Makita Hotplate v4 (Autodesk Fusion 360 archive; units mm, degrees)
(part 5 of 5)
sketch "Cam Thru" plane through (0, 21.7, 0) normal (0, 1, 0) x axis (-1, 0, 0)
  line L1 (0.8366, 36.2185) -> (-6.8436, 39.7998)
  line L2 (-1.1241, 49.7064) -> (5.8176, 44.8458)
  line L3 (-25.7201, 47.5685) -> (-23.2876, 49.6096)
  line L4 (-25.1687, 44.4413) -> (-25.7201, 47.5685)
  line L5 (-22.1848, 43.3553) -> (-25.1687, 44.4413)
  line L6 (-19.7522, 45.3964) -> (-22.1848, 43.3553)
  line L7 (-20.3036, 48.5236) -> (-19.7522, 45.3964)
  line L8 (-23.2876, 49.6096) -> (-20.3036, 48.5236)
  line L9 (-20, 54) -> (-22.7362, 46.4825)
  line L10 (-20, 70.55) -> (-20, 54)
  line L11 (6.1251, 40.75) -> (4.5374, 43.5)
  line L12 (4.5374, 38) -> (6.1251, 40.75)
  line L13 (1.362, 38) -> (4.5374, 38)
  line L14 (-0.2258, 40.75) -> (1.362, 38)
  line L15 (1.362, 43.5) -> (-0.2258, 40.75)
  line L16 (4.5374, 43.5) -> (1.362, 43.5)
  curve K1 (-11.8397, 39.6017) -> (-6.8436, 39.7998)
  curve K2 (-1.1241, 49.7064) -> (-3.4505, 54.1322)
  line L17 (-14.6263, 51.6906) -> (-10.6263, 49.3812)
  line L18 (-14.6263, 56.3094) -> (-14.6263, 51.6906)
  line L19 (-10.6263, 58.6188) -> (-14.6263, 56.3094)
  line L20 (-6.6263, 56.3094) -> (-10.6263, 58.6188)
  line L21 (-6.6263, 51.6906) -> (-6.6263, 56.3094)
  line L22 (-10.6263, 49.3812) -> (-6.6263, 51.6906)
  arc A1 centre (-20, 54) radius 16.55 clockwise from (-11.8397, 39.6017) to (-3.4505, 54.1322)
  arc A2 centre (2.9497, 40.75) radius 5 clockwise from (5.8176, 44.8458) to (0.8366, 36.2185)
  circle C1 centre (-22.7362, 46.4825) radius 3
  circle C2 centre (-22.7362, 46.4825) radius 1.625
  point P10 (-22.7362, 46.4825)
  point P18 (-22.7362, 46.4825)
  point P19 (-22.7362, 46.4825)
  point P4 (-20, 54)
  point P20 (-20, 54)
  point P22 (-20, 70.55)
  point P21 (-20, 54)
  point P15 (-22.1848, 43.3553)
  concentric C1 C2
  coincident P10 P18
  coincident P18 P19
  coincident P4 P20
  perpendicular L8 L9
  coincident A1 P22
  vertical L10
  coincident P20 P21
  dimension "d2589" diameter C1 = 6
  dimension "d2590" diameter C2 = 3.25
  dimension "d2591" distance P15 L8 = 5.5
  dimension "d2593" distance P19 P20 = 8
  dimension "d2795" = 200
extrude "Extrude241" cut sketch "Cam Thru" profile of C2 to an object
extrude "Extrude242" cut sketch "Cam Thru" profile of C2 L3 L4 L5 L6 L7 L8 to an object offset -20
chamfer "Chamfer34" distance 1.45
chamfer "Chamfer35" distance 1.5
circular_pattern "C-Pattern9" TotalAngle 360
sketch "Circuit City" plane through (0, 0, 0) normal (0, 1, 0) x axis (1, 0, 0)
  line L1 (-35, 0) -> (-35, -120)
  line L2 (-35, -120) -> (35, -120)
  line L3 (35, -120) -> (35, 0)
  line L4 (35, 0) -> (-35, 0)
  line L5 (-34.5, -45.6) -> (-34.5, -60)
  line L6 (-33.55, -45.6) -> (-34.5, -45.6)
  line L7 (-33.55, -43.6) -> (-33.55, -45.6)
  line L8 (-30.45, -43.6) -> (-33.55, -43.6)
  line L9 (-30.45, -44.1) -> (-30.45, -43.6)
  line L10 (-28, -44.1) -> (-30.45, -44.1)
  line L11 (-28, -23.5) -> (-28, -44.1)
  line L12 (-37.5, -23.5) -> (-28, -23.5)
  line L13 (-37.5, -60) -> (-37.5, -23.5)
  line L14 (-34.5, -60) -> (-37.5, -60)
  line L15 (-34.5, -74.4) -> (-34.5, -60)
  line L16 (-33.55, -74.4) -> (-34.5, -74.4)
  line L17 (-33.55, -76.4) -> (-33.55, -74.4)
  line L18 (-30.45, -76.4) -> (-33.55, -76.4)
  line L19 (-30.45, -75.9) -> (-30.45, -76.4)
  line L20 (-28, -75.9) -> (-30.45, -75.9)
  line L21 (-28, -96.5) -> (-28, -75.9)
  line L22 (-37.5, -96.5) -> (-28, -96.5)
  line L23 (-37.5, -60) -> (-37.5, -96.5)
  line L24 (-32, -76.4) -> (-32, -43.6)
  line L25 (-35.25, -23.5) -> (-35.25, -96.5)
  line L26 (-32, -89.2668) -> (-29.2, -90.8834)
  line L27 (-34.8, -90.8834) -> (-32, -89.2668)
  line L28 (-34.8, -94.1166) -> (-34.8, -90.8834)
  line L29 (-32, -95.7332) -> (-34.8, -94.1166)
  line L30 (-29.2, -94.1166) -> (-32, -95.7332)
  line L31 (-29.2, -90.8834) -> (-29.2, -94.1166)
  line L32 (-34.8, -29.1166) -> (-32, -30.7332)
  line L33 (-34.8, -25.8834) -> (-34.8, -29.1166)
  line L34 (-32, -24.2668) -> (-34.8, -25.8834)
  line L35 (-29.2, -25.8834) -> (-32, -24.2668)
  line L36 (-32, -30.7332) -> (-29.2, -29.1166)
  line L37 (-29.2, -29.1166) -> (-29.2, -25.8834)
  line L38 (-38, -39.5) -> (-38, -80.5)
  line L39 (-38, -39.5) -> (-38, -22.5)
  line L40 (-38, -97.5) -> (-38, -80.5)
  line L41 (-20, -22.5) -> (-38, -22.5)
  line L42 (-20, -23.5) -> (-20, -22.5)
  line L43 (-28, -23.5) -> (-20, -23.5)
  line L44 (-37, -40.5) -> (-38, -40.5)
  line L45 (-37, -23.5) -> (-37, -40.5)
  line L46 (-27.5, -25.17) -> (-20, -25.17)
  line L47 (-27.5, -94.83) -> (-27.5, -25.17)
  line L48 (-20, -26.17) -> (-20, -25.17)
  line L49 (-26.75, -26.17) -> (-20, -26.17)
  line L50 (-26.75, -93.83) -> (-26.75, -26.17)
  line L51 (-20, -93.83) -> (-26.75, -93.83)
  line L52 (-20, -94.83) -> (-20, -93.83)
  line L53 (-27.5, -94.83) -> (-20, -94.83)
  line L54 (-37, -79.5) -> (-38, -79.5)
  line L55 (-37, -96.5) -> (-37, -79.5)
  line L56 (-28, -96.5) -> (-20, -96.5)
  line L57 (-20, -97.5) -> (-38, -97.5)
  line L58 (-20, -97.5) -> (-20, -96.5)
  line L59 (-30.45, -45.6) -> (-33.55, -45.6)
  line L60 (-30.45, -44.1) -> (-30.45, -45.6)
  line L61 (-30.45, -74.4) -> (-33.55, -74.4)
  line L62 (-30.45, -75.9) -> (-30.45, -74.4)
  line L63 (-14.5, -120) -> (-14.5, -22.5)
  line L64 (-14.5, -22.5) -> (-20, -22.5)
  line L65 (-36, -120) -> (-35, -120)
  line L66 (-36, -97.5) -> (-36, -120)
  circle C1 centre (-32, -92.5) radius 1.625
  circle C2 centre (-32, -92.5) radius 3
  circle C3 centre (-32, -27.5) radius 1.625
  circle C4 centre (-32, -27.5) radius 3
  circle C5 centre (-25, -108) radius 4.25
  point P10 (-34.5, -60)
  point P20 (-34.5, -60)
  point P21 (-34.5, -60)
  point P11 (-34.5, -45.6)
  point P22 (-34.5, -74.4)
  point P12 (-33.55, -45.6)
  point P23 (-33.55, -74.4)
  point P13 (-33.55, -43.6)
  point P24 (-33.55, -76.4)
  point P14 (-30.45, -43.6)
  point P25 (-30.45, -76.4)
  point P15 (-30.45, -44.1)
  point P26 (-30.45, -75.9)
  point P16 (-28, -44.1)
  point P27 (-28, -75.9)
  point P17 (-28, -23.5)
  point P28 (-28, -96.5)
  point P18 (-37.5, -23.5)
  point P29 (-37.5, -96.5)
  point P19 (-37.5, -60)
  point P30 (-37.5, -60)
  point P31 (-32, -43.6)
  point P32 (-32, -43.6)
  point P33 (-32, -76.4)
  point P34 (-32, -60)
  point P35 (-35.25, -96.5)
  point P36 (-35.25, -23.5)
  point P37 (-32, -92.5)
  point P45 (-32, -92.5)
  point P38 (-32, -92.5)
  point P39 (-29.2, -90.8834)
  point P52 (-29.2, -29.1166)
  point P40 (-32, -89.2668)
  point P47 (-32, -30.7332)
  point P41 (-34.8, -90.8834)
  point P48 (-34.8, -29.1166)
  point P42 (-34.8, -94.1166)
  point P49 (-34.8, -25.8834)
  point P43 (-32, -95.7332)
  point P50 (-32, -24.2668)
  point P44 (-29.2, -94.1166)
  point P51 (-29.2, -25.8834)
  point P61 (-28, -23.5)
  point P58 (-38, -22.5)
  point P62 (-38, -40.5)
  point P64 (-37, -23.5)
  point P67 (-27.5, -94.83)
  point P73 (-27.5, -94.83)
  point P60 (-20, -23.5)
  point P74 (-38, -79.5)
  point P78 (-28, -96.5)
  point P63 (-37, -40.5)
  point P76 (-37, -96.5)
  point P79 (-38, -97.5)
  point P72 (-20, -94.83)
  point P82 (-30.45, -44.1)
  point P84 (-30.45, -75.9)
  point P86 (-14.5, -120)
  point P85 (-14.5, -22.5)
  point P87 (-14.5, -22.5)
  point P2 (-35, -120)
  point P89 (-35, -120)
  point P91 (-36, -97.5)
  point P65 (-20, -25.17)
  point P68 (-20, -26.17)
  point P55 (-38, -39.5)
  point P54 (-38, -80.5)
  point P77 (-20, -96.5)
  point P88 (-25, -108)
  point P90 (-36, -120)
  vertical L5
  perpendicular L5 L6
  perpendicular L6 L7
  perpendicular L7 L8
  perpendicular L8 L9
  perpendicular L9 L10
  perpendicular L10 L11
  perpendicular L11 L12
  perpendicular L12 L13
  perpendicular L11 L14
  coincident P10 P20
  symmetric P10 L14 P21
  symmetric P11 L14 P22
  symmetric P12 L14 P23
  symmetric P13 L14 P24
  symmetric P14 L14 P25
  symmetric P15 L14 P26
  symmetric P16 L14 P27
  symmetric P17 L14 P28
  symmetric P18 L14 P29
  symmetric P19 L14 P30
  midpoint L8 P31
  coincident P31 P32
  midpoint L18 P33
  midpoint L24 P34
  coincident L22 P35
  coincident L12 P36
  perpendicular L12 L25
  concentric C1 C2
  coincident P37 P45
  vertical L31
  coincident L24 P38
  symmetric L14 C1 C3
  symmetric L14 C2 C4
  symmetric L14 P39 P52
  symmetric L14 P40 P47
  symmetric L14 P41 P48
  symmetric L14 P42 P49
  symmetric L14 P43 P50
  symmetric L14 P44 P51
  perpendicular L41 L42
  coincident L11 P61
  perpendicular L11 L43
  coincident P17 P61
  coincident L39 P58
  coincident L38 P62
  perpendicular L38 L44
  coincident L12 P64
  perpendicular L12 L45
  horizontal L41
  horizontal L46
  perpendicular L46 L47
  perpendicular L46 L48
  perpendicular L48 L49
  perpendicular L49 L50
  perpendicular L48 L51
  perpendicular L51 L52
  perpendicular L52 L53
  coincident P67 P73
  coincident P60 L48
  equal L48 L52
  coincident L38 P74
  perpendicular L23 L54
  perpendicular L22 L55
  coincident P28 P78
  coincident P63 L55
  coincident L22 P76
  coincident L40 P79
  perpendicular L40 L57
  vertical L58
  coincident P72 L58
  coincident P60 L52
  horizontal L56
  perpendicular L24 L59
  perpendicular L59 L60
  coincident P15 P82
  perpendicular L24 L61
  perpendicular L61 L62
  coincident P26 P84
  coincident L2 P86
  perpendicular L2 L63
  perpendicular L42 L64
  coincident P85 P87
  coincident P2 P89
  perpendicular L1 L65
  coincident L57 P91
  perpendicular L57 L66
  dimension "d2656" distance P13 P14 = 3.1
  dimension "d2657" distance L8 P25 = 32.8 (= "32.7 mm + 0.1 mm")
  dimension "d2659" distance L5 P31 = 2.5 (= "( 4.8 / 2 ) * 1 mm + 0.1 mm")
  dimension "d2661" distance L6 P23 = 28.8 (= "28.7 mm + 0.1 mm")
  dimension "d2662" distance P14 L10 = 0.5
  dimension "d2663" distance L1 P34 = 3
  dimension "d2664" distance L1 P30 = 2.5
  dimension "d2666" distance L4 P34 = 60
  dimension "d2667" distance P18 P29 = 73
  dimension "d2668" distance L1 L25 = 0.25
  dimension "d2669" diameter C1 = 3.25
  dimension "d2670" distance L1 P17 = 7
  dimension "d2671" diameter C2 = 6
  dimension "d2672" distance P42 P44 = 5.6
  dimension "d2673" distance P34 P37 = 32.5
  dimension "d2699" distance P62 P63 = 1
  dimension "d2700" distance L41 P64 = 1
  dimension "d2701" distance P60 P61 = 8
  dimension "d2702" distance L11 L47 = 0.5
  dimension "d2703" distance L43 L46 = 1.67
  dimension "d2704" distance P65 P68 = 1
  dimension "d2705" distance L47 L50 = 0.75
  dimension "d2706" distance P55 P62 = 1 (= "d2699")
  dimension "d2707" distance P54 L54 = 1
  dimension "d2708" distance P29 L57 = 1 (= "d2700")
  dimension "d2709" distance L53 P77 = 1.67 (= "d2703")
  dimension "d2861" distance P38 L63 = 17.5
  dimension "d2865" distance P37 P88 = 7
  dimension "d2866" distance P45 P88 = 15.5
  dimension "d2867" diameter C5 = 8.5
  dimension "d2868" distance P89 P90 = 1
extrude "Extrude264" cut sketch "Circuit City" profile of L1 L2 L5 L6 L7 L8 L9 L10 L11 L12 L13 L15 L16 L17 L18 L19 L20 L21 L22 L23 L25 C1 L26 L27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 to an object offset 2.5
extrude "Extrude248" sketch "Circuit City" profile of L1 L5 L6 L7 L8 L9 L10 L11 L12 L15 L16 L17 L18 L19 L20 L21 L22 L25 C1 L26 L27 L28 L29 L30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 blind -6.75 from offset 1.6 bodies "Circuit Cap"
extrude "Extrude249" sketch "Circuit City" profile of L12 L13 L22 L23 L25 L44 L45 L54 L55 to an object from offset 0.1
extrude "Extrude251" cut sketch "Circuit City" profile of C1 C3 to an object
extrude "Extrude256" sketch "Circuit City" profile of L1 L5 L6 L7 L8 L9 L10 L11 L12 L13 L15 L16 L17 L18 L19 L20 L21 L22 L23 L25 C1 L26 L27 L28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 blind -0.5
extrude "Extrude250" sketch "Circuit City" profile of C1 L26 L27 L28 L29 L30 L31 C3 L32 L33 L34 L35 L36 L37 to an object offset 15
fillet "Fillet121" radius 2
chamfer "Chamfer44" distance 1.6
chamfer "Chamfer48" distance 1.45
extrude "Extrude252" sketch "Circuit City" profile of L1 L12 L13 L22 L23 L38 L39 L40 L41 L42 L43 L44 L45 L46 L47 L48 L49 L50 L51 L52 L53 L54 L55 L56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 to an object
fillet "Fillet122" radius 0.5
sketch "Pushrod Space" plane through (0, 22.2, 0) normal (0, 1, 0) x axis (-1, 0, 0)
  line L1 (41.5262, 38.2356) -> (39.8025, 35.25)
  line L2 (44.9738, 38.2356) -> (41.5262, 38.2356)
  line L3 (46.6975, 35.25) -> (44.9738, 38.2356)
  line L4 (44.9738, 32.2644) -> (46.6975, 35.25)
  line L5 (41.5262, 32.2644) -> (44.9738, 32.2644)
  line L6 (39.8025, 35.25) -> (41.5262, 32.2644)
  line L7 (49.8025, 84.75) -> (51.5262, 81.7644)
  line L8 (51.5262, 87.7356) -> (49.8025, 84.75)
  line L9 (54.9738, 87.7356) -> (51.5262, 87.7356)
  line L10 (56.6975, 84.75) -> (54.9738, 87.7356)
  line L11 (54.9738, 81.7644) -> (56.6975, 84.75)
  line L12 (51.5262, 81.7644) -> (54.9738, 81.7644)
  line L13 (56.6975, 35.25) -> (54.9738, 38.2356)
  line L14 (54.9738, 32.2644) -> (56.6975, 35.25)
  line L15 (51.5262, 32.2644) -> (54.9738, 32.2644)
  line L16 (49.8025, 35.25) -> (51.5262, 32.2644)
  line L17 (51.5262, 38.2356) -> (49.8025, 35.25)
  line L18 (54.9738, 38.2356) -> (51.5262, 38.2356)
  line L19 (46.6975, 84.75) -> (44.9738, 87.7356)
  line L20 (44.9738, 81.7644) -> (46.6975, 84.75)
  line L21 (41.5262, 81.7644) -> (44.9738, 81.7644)
  line L22 (39.8025, 84.75) -> (41.5262, 81.7644)
  line L23 (41.5262, 87.7356) -> (39.8025, 84.75)
  line L24 (44.9738, 87.7356) -> (41.5262, 87.7356)
  line L25 (-35, 120) -> (58.5, 120)
  line L26 (-35, 0) -> (-35, 120)
  line L27 (58.5, 0) -> (-35, 0)
  line L28 (58.5, 39.5) -> (58.5, 0)
  line L29 (49.25, 39.5) -> (58.5, 39.5)
  line L30 (49.25, 34.25) -> (49.25, 39.5)
  line L31 (47.25, 39.5) -> (47.25, 34.25)
  line L32 (38.5, 39.5) -> (47.25, 39.5)
  line L33 (47.25, 80.5) -> (38, 80.5)
  line L34 (47.25, 85.75) -> (47.25, 80.5)
  line L35 (49.25, 80.5) -> (49.25, 85.75)
  line L36 (58.5, 80.5) -> (49.25, 80.5)
  line L37 (58.5, 120) -> (58.5, 80.5)
  line L38 (38.5, 39.5) -> (28.5, 39.5)
  line L39 (48.25, 49.75) -> (48.25, 34.25)
  line L40 (-6.5566, 23.8624) -> (-20, 54)
  line L41 (-39.9714, 27.7295) -> (-37.8295, 32.5403)
  line L42 (-37.8295, 32.5403) -> (-34.173, 40.7529)
  line L43 (28.5, 39.5) -> (-6.5566, 23.8624)
  line L44 (10.847, 42.2757) -> (6.4974, 45.2651)
  line L45 (-0.9412, 50.3775) -> (6.4974, 45.2651)
  line L46 (-45, 0) -> (-35, 0)
  line L47 (-45, 120) -> (-45, 0)
  line L48 (-35, 120) -> (-45, 120)
  line L49 (7.9, 54) -> (-20, 54)
  line L50 (3.9, 50.8246) -> (1.15, 52.4123)
  line L51 (6.65, 52.4123) -> (3.9, 50.8246)
  line L52 (6.65, 55.5877) -> (6.65, 52.4123)
  line L53 (3.9, 57.1754) -> (6.65, 55.5877)
  line L54 (1.15, 55.5877) -> (3.9, 57.1754)
  line L55 (1.15, 52.4123) -> (1.15, 55.5877)
  line L56 (17.368, 47.0482) -> (48.25, 49.75)
  line L57 (38, 79.5) -> (38, 40.5)
  line L58 (26.75, 71.2668) -> (4.8491, 46.3979)
  line L59 (27.5, 84.2668) -> (37, 84.2668)
  line L60 (20.5, 96.5) -> (36.5, 96.5)
  line L61 (37.5, 97.5) -> (20.5, 97.5)
  line L62 (38, 80.5) -> (38, 97)
  line L63 (38, 23) -> (38, 39)
  line L64 (20.5, 22.5) -> (37.5, 22.5)
  line L65 (36.5, 23.5) -> (20.5, 23.5)
  line L66 (37, 40) -> (37, 24)
  line L67 (38, 40.5) -> (37.5, 40.5)
  line L68 (37.5, 79.5) -> (38, 79.5)
  line L69 (37, 96) -> (37, 80)
  line L70 (29.2, 29.1166) -> (29.2, 25.8834)
  line L71 (32, 30.7332) -> (29.2, 29.1166)
  line L72 (34.8, 29.1166) -> (32, 30.7332)
  line L73 (34.8, 25.8834) -> (34.8, 29.1166)
  line L74 (32, 24.2668) -> (34.8, 25.8834)
  line L75 (29.2, 25.8834) -> (32, 24.2668)
  line L76 (32, 95.7332) -> (29.2, 94.1166)
  line L77 (34.8, 94.1166) -> (32, 95.7332)
  line L78 (34.8, 90.8834) -> (34.8, 94.1166)
  line L79 (32, 89.2668) -> (34.8, 90.8834)
  line L80 (29.2, 90.8834) -> (32, 89.2668)
  line L81 (29.2, 94.1166) -> (29.2, 90.8834)
  line L82 (20.5, 93.83) -> (26.25, 93.83)
  line L83 (27, 94.83) -> (20.5, 94.83)
  line L84 (27.5, 25.67) -> (27.5, 94.33)
  line L85 (20.5, 25.17) -> (27, 25.17)
  line L86 (26.25, 26.17) -> (20.5, 26.17)
  line L87 (26.75, 93.33) -> (26.75, 26.67)
  line L88 (6.1199, 25.17) -> (20.5, 25.17)
  line L89 (20.0025, 94.3798) -> (16.5264, 59.6577)
  closed curve K1 centre (52.9954, 12)
  closed curve K2 centre (52.9954, 108)
  arc A1 centre (48.25, 34.25) radius 1 clockwise from (49.25, 34.25) to (47.25, 34.25)
  arc A2 centre (48.25, 85.75) radius 1 clockwise from (47.25, 85.75) to (49.25, 85.75)
  arc A3 centre (-20, 54) radius 33 clockwise from (-6.5566, 23.8624) to (-39.9714, 27.7295)
  arc A4 centre (-17.0001, 85.9192) radius 65 clockwise from (28.5, 39.5) to (-20.2611, 21.001)
  arc A5 centre (-20, 54) radius 33 clockwise from (10.847, 42.2757) to (-6.5566, 23.8624)
  arc A6 centre (-20, 54) radius 19.4 clockwise from (-34.173, 40.7529) to (-0.9412, 50.3775)
  circle C1 centre (3.9, 54) radius 1.625
  circle C2 centre (3.9, 54) radius 3
  circle C3 centre (-20, 54) radius 27.9
  arc A7 centre (-20, 54) radius 20.9 clockwise from (-34.8313, 39.2744) to (0.4, 49.4557)
  arc A8 centre (36.5, 96) radius 0.5 clockwise from (36.5, 96.5) to (37, 96)
  arc A9 centre (20.5, 97) radius 0.5 clockwise from (20.5, 96.5) to (20.5, 97.5)
  arc A10 centre (37.5, 97) radius 0.5 clockwise from (37.5, 97.5) to (38, 97)
  arc A11 centre (38.5, 39) radius 0.5 clockwise from (38, 39) to (38.5, 39.5)
  arc A12 centre (37.5, 23) radius 0.5 clockwise from (38, 23) to (37.5, 22.5)
  arc A13 centre (20.5, 23) radius 0.5 clockwise from (20.5, 22.5) to (20.5, 23.5)
  arc A14 centre (36.5, 24) radius 0.5 clockwise from (37, 24) to (36.5, 23.5)
  arc A15 centre (37.5, 40) radius 0.5 clockwise from (37, 40) to (37.5, 40.5)
  arc A16 centre (37.5, 80) radius 0.5 clockwise from (37.5, 79.5) to (37, 80)
  arc A17 centre (26.25, 93.33) radius 0.5 clockwise from (26.25, 93.83) to (26.75, 93.33)
  arc A18 centre (20.5, 94.33) radius 0.5 clockwise from (20.5, 93.83) to (20.5, 94.83)
  arc A19 centre (27, 94.33) radius 0.5 clockwise from (27, 94.83) to (27.5, 94.33)
  arc A20 centre (27, 25.67) radius 0.5 clockwise from (27.5, 25.67) to (27, 25.17)
  arc A21 centre (20.5, 25.67) radius 0.5 clockwise from (20.5, 25.17) to (20.5, 26.17)
  arc A22 centre (26.25, 26.67) radius 0.5 clockwise from (26.75, 26.67) to (26.25, 26.17)
  point P46 (48.25, 34.25)
  point P47 (48.25, 34.25)
  point P50 (-20, 54)
  point P88 (-20, 54)
  point P53 (-20, 54)
  point P54 (-37.8295, 32.5403)
  point P56 (-37.8295, 32.5403)
  point P51 (-39.9714, 27.7295)
  point P55 (-39.9714, 27.7295)
  point P63 (28.5, 39.5)
  point P62 (-20.2611, 21.001)
  point P64 (-20, 54)
  point P49 (6.4974, 45.2651)
  point P67 (6.4974, 45.2651)
  point P52 (-6.5566, 23.8624)
  point P65 (-6.5566, 23.8624)
  point P30 (-35, 0)
  point P70 (-35, 0)
  point P29 (-35, 120)
  point P73 (-35, 120)
  point P77 (-20, 54)
  point P78 (7.9, 54)
  point P79 (3.9, 54)
  point P87 (3.9, 54)
  point P60 (28.5, 39.5)
  point P45 (38.5, 39.5)
  point P59 (38.5, 39.5)
  point P92 (0.9, 54)
  point P95 (4.8491, 46.3979)
  point P97 (2.275, 54)
  point P48 (48.25, 49.75)
  point P93 (48.25, 49.75)
  point P100 (27.5, 84.2668)
  point P157 (37, 84.2668)
  point P96 (26.75, 71.2668)
  point P151 (20.5, 25.17)
  point P158 (20.5, 25.17)
  point P159 (6.1199, 25.17)
  point P160 (16.5264, 59.6577)
  point P161 (20.0025, 94.3798)
  point P71 (-45, 0)
  point P84 (6.65, 55.5877)
  point P80 (3.9, 54)
  point P94 (17.368, 47.0482)
  point P137 (32, 89.2668)
  horizontal L38
  coincident P46 P47
  parallel L30 L39
  coincident P50 P88
  coincident P53 P88
  coincident P54 C3
  coincident P54 P56
  parallel L41 L42
  coincident P51 P55
  tangent A3 L43
  coincident L43 P63
  coincident A3 P62
  coincident P50 P64
  coincident P49 P67
  parallel L44 L45
  coincident P52 P65
  coincident P30 P70
  perpendicular L26 L46
  perpendicular L46 L47
  perpendicular L47 L48
  coincident P29 P73
  coincident P77 P88
  coincident P78 C3
  coincident L49 P79
  concentric C1 C2
  coincident P79 P87
  perpendicular L49 L55
  coincident L38 P60
  coincident P45 P59
  coincident A7 P92
  coincident L49 P92
  coincident L45 P95
  horizontal L49
  coincident C1 P97
  coincident L49 P97
  coincident P60 P63
  coincident P48 P93
  coincident P100 L84
  coincident L69 P157
  horizontal L59
  coincident P96 L87
  coincident P151 P158
  coincident A4 P159
  horizontal L88
  coincident L58 P160
  coincident A18 P161
  tangent A18 L89
  dimension "d2536" distance P47 P48 = 15.5
  dimension "d2538" radius A3 = 33
  dimension "d2539" distance P59 P60 = 10
  dimension "d2540" distance P52 P62 = 14
  dimension "d2543" radius A4 = 65
  dimension "d2588" distance P70 P71 = 10
  dimension "d2603" distance P84 L55 = 5.5
  dimension "d2604" diameter C2 = 6
  dimension "d2605" diameter C1 = 3.25
  dimension "d2636" distance L55 P92 = 0.25
  dimension "d2638" angle L39 L56 = 85
  dimension "d2741" distance P67 P95 = 2
  dimension "d2746" distance P80 P92 = 3
  dimension "d2747" distance P92 P97 = 1.375
  dimension "d2756" distance P93 P94 = 31
  dimension "d2757" distance P96 L59 = 13
  dimension "d2860" distance L59 P137 = 5
  dimension "d2870" distance P80 L89 = 12
extrude "Extrude257" cut sketch "Pushrod Space" profile of L26 C3 L42 L45 A6 C1 L50 L51 L52 L53 L54 L55 A7 L58 to an object
extrude "Extrude258" cut sketch "Pushrod Space" profile of C3 L47 to an object
extrude "Extrude259" new body sketch "Pushrod Space" profile of L26 C3 A3 L41 L46 L47 L48 to an object
combine "Combine30" bodies "Rotary Cap"
offset_faces "OffsetFaces16" distance -0.25
extrude "Extrude237" cut sketch "Pushrod Space" profile of L26 C3 A3 L43 A4 A5 L44 L45 L58 to an object
chamfer "Chamfer49" distance 2
extrude "Extrude260" cut sketch "Pushrod Space" profile of L38 A3 L43 A4 L57 L59 L66 A15 L67 L68 A16 L69 L84 A21 L86 A22 L87 L88 to an object offset 1
fillet "Fillet125" radius 7
fillet "Fillet126" radius 3
fillet "Fillet128" radius 1
extrude "Extrude243" cut sketch "Pushrod Space" profile of C1 to an object
extrude "Extrude244" sketch "Pushrod Space" profile of C1 L50 L51 L52 L53 L54 L55 blind 4.5
chamfer "Chamfer36" distance 0.5
chamfer "Chamfer37" distance 1.5
circular_pattern "C-Pattern8" countU 12 TotalAngle 360
sketch "Sketch82" plane through (0, 0, 0) normal (0, 1, 0) x axis (1, 0, 0)
  line L1 (-31.75, -107) -> (23.25, -107)
  line L2 (-31.75, -22) -> (-31.75, -107)
  line L3 (23.25, -22) -> (-31.75, -22)
  line L4 (23.25, -107) -> (23.25, -22)
  line L5 (8.25, -8) -> (8.25, -22)
  line L6 (-21.75, -8) -> (8.25, -8)
  line L7 (-21.75, -22) -> (-21.75, -8)
  line L8 (-11.75, -62) -> (-11.75, -107)
  line L9 (45, 0) -> (-58.5, 0)
  line L10 (-6.75, 0) -> (-6.75, -8)
  line L11 (-1.75, -90) -> (-1.75, 0)
  line L12 (17.25, -90) -> (-17.75, -90)
  line L13 (-1.75, -92.9585) -> (1.75, -94.9793)
  line L14 (-5.25, -94.9793) -> (-1.75, -92.9585)
  line L15 (-5.25, -99.0207) -> (-5.25, -94.9793)
  line L16 (-1.75, -101.0415) -> (-5.25, -99.0207)
  line L17 (1.75, -99.0207) -> (-1.75, -101.0415)
  line L18 (1.75, -94.9793) -> (1.75, -99.0207)
  line L19 (17.25, -8) -> (8.25, -8)
  circle C1 centre (-21.75, -8) radius 2.125
  circle C2 centre (8.25, -8) radius 2.125
  circle C3 centre (8.25, -8) radius 4.125
  circle C4 centre (23.25, -107) radius 2.125
  circle C5 centre (-31.75, -107) radius 2.125
  circle C6 centre (-31.75, -107) radius 4.5
  circle C7 centre (-11.75, -62) radius 2.125
  circle C8 centre (-16.75, -107) radius 2.125
  circle C9 centre (23.25, -107) radius 4.125
  circle C10 centre (-16.75, -107) radius 4.125
  circle C11 centre (-11.75, -62) radius 4.125
  circle C12 centre (-21.75, -8) radius 4.125
  circle C13 centre (-17.75, -90) radius 2.125
  circle C14 centre (17.25, -90) radius 2.125
  circle C15 centre (-17.75, -90) radius 4.125
  circle C16 centre (17.25, -90) radius 4.125
  circle C17 centre (-1.75, -97) radius 2.075
  circle C18 centre (17.25, -8) radius 2.125
  circle C19 centre (17.25, -8) radius 4.125
  point P6 (8.25, -22)
  point P9 (-21.75, -22)
  point P10 (-6.75, -8)
  point P8 (-21.75, -8)
  point P11 (-21.75, -8)
  point P7 (8.25, -8)
  point P12 (8.25, -8)
  point P2 (23.25, -107)
  point P14 (23.25, -107)
  point P3 (-31.75, -107)
  point P15 (-31.75, -107)
  point P17 (-11.75, -107)
  point P18 (-11.75, -62)
  point P19 (-11.75, -62)
  point P22 (-6.75, 0)
  point P23 (-6.75, -8)
  point P24 (-6.75, 0)
  point P25 (-16.75, -107)
  point P26 (23.25, -107)
  point P27 (-16.75, -107)
  point P28 (-11.75, -62)
  point P29 (-21.75, -8)
  point P30 (-1.75, 0)
  point P32 (-17.75, -90)
  point P36 (-17.75, -90)
  point P33 (17.25, -90)
  point P37 (17.25, -90)
  point P38 (-1.75, -97)
  point P45 (-1.75, -97)
  point P48 (8.25, -8)
  point P46 (17.25, -8)
  point P49 (17.25, -8)
  point P31 (-1.75, -90)
  point P1 (0, 0)
  point P44 (1.75, -99.0207)
  point P21 (45, 0)
  point P35 (17.25, -90)
  point P34 (-17.75, -90)
  point P47 (17.25, -8)
  horizontal L1
  vertical L2
  horizontal L3
  vertical L4
  coincident L3 P6
  perpendicular L3 L5
  perpendicular L5 L6
  perpendicular L3 L7
  coincident L3 P9
  midpoint L6 P10
  coincident P8 P11
  coincident P7 P12
  equal C1 C2
  concentric C2 C3
  coincident P2 P14
  coincident P3 P15
  equal C2 C5
  equal C2 C4
  concentric C5 C6
  coincident L1 P17
  perpendicular L1 L8
  coincident P18 P19
  equal C2 C7
  midpoint L9 P22
  coincident P10 P23
  coincident P22 P24
  perpendicular L9 L10
  coincident L1 P25
  equal C5 C8
  equal C9 C11
  equal C9 C12
  equal C10 C12
  equal C3 C9
  coincident P14 P26
  coincident P25 P27
  coincident P19 P28
  coincident P11 P29
  coincident L9 P30
  perpendicular L9 L11
  horizontal L12
  concentric C13 C15
  concentric C14 C16
  coincident P32 P36
  coincident P33 P37
  equal C8 C13
  equal C10 C15
  equal C9 C16
  equal C4 C14
  coincident P38 P45
  vertical L18
  concentric C18 C19
  equal C2 C18
  equal C3 C19
  coincident P12 P48
  parallel L6 L19
  coincident P46 P49
  coincident P31 L12
  dimension "d2834" distance P2 P3 = 55
  dimension "d2836" distance P1 L3 = 22
  dimension "d2838" distance P7 P8 = 30
  dimension "d2839" diameter C2 = 4.25
  dimension "d2840" diameter C3 = 8.25
  dimension "d2841" distance P17 P18 = 45
  dimension "d2845" distance L4 P22 = 30
  dimension "d2846" diameter C6 = 9
  dimension "d2879" distance L6 L9 = 8
  dimension "d2880" distance P22 P27 = 107
  dimension "d2883" distance P19 P22 = 62
  dimension "d2885" distance P30 P31 = 90
  dimension "d2887" distance P22 P30 = 5
  dimension "d2888" diameter C17 = 4.15
  dimension "d2889" distance P44 L15 = 7 (= "hw_m4hex_d")
  dimension "d2890" distance P22 P45 = 97
  dimension "d2891" distance P22 P45 = 5
  dimension "d2896" distance L1 P21 = 107
  dimension "d2900" distance P22 P35 = 24
  dimension "d2901" distance P22 P34 = 11
  dimension "d2902" distance P10 L8 = 5
  dimension "d2903" distance P22 P27 = 10
  dimension "d2904" distance P10 P47 = 24
extrude "Extrude262" cut sketch "Sketch82" profile of C1 C2 C4 C7 C8 C13 C14 C17 C18 to an object
extrude "Extrude265" sketch "Sketch82" profile of C1 C2 C3 C4 C7 C8 C9 C10 C11 C12 C13 C14 C15 C16 C18 C19 to an object from offset -0.25
chamfer "Chamfer54" distance 2 (= "( ( 8.25 - 4.25 ) / 2 ) * 1 mm")
fillet "Fillet134" radius 1
extrude "Extrude267" sketch "Sketch82" profile of C17 L13 L14 L15 L16 L17 L18 blind 8
component_from_bodies "Body->Comp5"
component_from_bodies "Body->Comp6"
joint "Assemble65" alignAngle 0 alignOffsetX 0 alignOffsetY 0 alignOffsetZ -0.5
joint "Assemble66" alignAngle 0 alignOffsetX 0 alignOffsetY 0 alignOffsetZ 0
component_insert "Component Insert64"
joint "Assemble58" alignAngle 0 alignOffsetX 0 alignOffsetY 0 alignOffsetZ 0
component_insert "Component Insert65"
joint "Assemble59" alignAngle 180 alignOffsetX 0 alignOffsetY 0 alignOffsetZ 0
component_insert "Component Insert68"
joint "Assemble67" alignAngle 180 alignOffsetX 0 alignOffsetY 0 alignOffsetZ 0
joint "Assemble68" alignAngle 180 alignOffsetX 0 alignOffsetY 0 alignOffsetZ 0
component_insert "Component Insert78"
joint "Assemble78" alignAngle 180 alignOffsetX 0 alignOffsetY 0 alignOffsetZ 0
component_insert "Component Insert79"
joint "Assemble79" alignAngle 0 alignOffsetX 0 alignOffsetY 0 alignOffsetZ -2
component_insert "Component Insert80"
joint "Assemble80" alignAngle 180 alignOffsetX 0 alignOffsetY 0 alignOffsetZ 0
component_insert "Component Insert81"
joint "Assemble81" alignAngle 180 alignOffsetX 0 alignOffsetY 0 alignOffsetZ 0
component_insert "Component Insert82"
joint "Assemble82" alignAngle 180 alignOffsetX 0 alignOffsetY 0 alignOffsetZ 0
component_insert "Component Insert83"
joint "Assemble83" alignAngle 180 alignOffsetX 0 alignOffsetY 0 alignOffsetZ 0
component_insert "Component Insert84"
joint "Assemble84" alignAngle 150 alignOffsetX 0 alignOffsetY 0 alignOffsetZ 0
component_insert "Component Insert85"
joint "Assemble85" alignAngle 210 alignOffsetX 0 alignOffsetY 0 alignOffsetZ 0
component_insert "Component Insert86"
joint "Assemble86" alignAngle 170 alignOffsetX 0 alignOffsetY 0 alignOffsetZ -1.5
component_insert "Component Insert87"
joint "Assemble87" alignAngle 200 alignOffsetX 0 alignOffsetY 0 alignOffsetZ -1.5
component_insert "Component Insert88"
joint "Assemble88" alignAngle 0 alignOffsetX 0 alignOffsetY 0 alignOffsetZ 0
component_insert "Component Insert89"
joint "Assemble89" alignAngle 0 alignOffsetX 0 alignOffsetY 0 alignOffsetZ 0
component_insert "Component Insert90"
joint "Assemble90" alignAngle 0 alignOffsetX 0 alignOffsetY 0 alignOffsetZ -1.5
component_insert "Component Insert91"
joint "Assemble91" alignAngle 0 alignOffsetX 0 alignOffsetY 0 alignOffsetZ -1.5
component_insert "Component Insert92"
joint "Assemble92" alignAngle 30 alignOffsetX 0 alignOffsetY 0 alignOffsetZ -2
component_insert "Component Insert93"
joint "Assemble93" alignAngle 0 alignOffsetX 0 alignOffsetY 0 alignOffsetZ 0
component_insert "Component Insert94"
joint "Assemble94" alignAngle 0 alignOffsetX 0 alignOffsetY 0 alignOffsetZ 0
component_insert "Component Insert76"
joint "Assemble76" alignAngle 180 alignOffsetX 0 alignOffsetY 0 alignOffsetZ 0
component_insert "Component Insert77"
joint "Assemble77" alignAngle 180 alignOffsetX 0 alignOffsetY 0 alignOffsetZ 0
component_insert "Component Insert95"
joint "Assemble95" alignAngle 180 alignOffsetX 0 alignOffsetY 0 alignOffsetZ 0
component_insert "Component Insert97"
joint "Assemble96" alignAngle 180 alignOffsetX 0 alignOffsetY 0 alignOffsetZ 0
component_insert "Component Insert98"
joint "Assemble97" alignAngle 0 alignOffsetX 0 alignOffsetY 0 alignOffsetZ 0
component_insert "Component Insert99"
joint "Assemble98" alignAngle 0 alignOffsetX 0 alignOffsetY 0 alignOffsetZ 0
component_insert "Component Insert71"
joint "Assemble70" alignAngle 0 alignOffsetX 0 alignOffsetY 0 alignOffsetZ 0
component_insert "Component Insert72"
joint "Assemble72" alignAngle 180 alignOffsetX 0 alignOffsetY 0 alignOffsetZ 0
component_insert "Component Insert70"
joint "Assemble71" alignAngle 0 alignOffsetX 0 alignOffsetY 0 alignOffsetZ 0 DistanceMinimum 0 DistanceMaximum 0
component_insert "Component Insert100"
joint "Assemble99" alignAngle 0 alignOffsetX 0 alignOffsetY 0 alignOffsetZ 0
component_insert "Component Insert102"
joint "Assemble100" alignAngle 0 alignOffsetX 0 alignOffsetY 0 alignOffsetZ 0
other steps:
base_feature "Base Feature1" bodies "HP Cam Rear"
base_feature "Base Feature1" bodies "HP Cam Front"
step "Combine15"
step "Combine16"
step "Revolve" AlongAngle 360
remove_body "Mirror7" mirrorStitchTolerance 0.1
step "Sweep2" TwistAngle 0 TaperAngle 0
step "Sweep3" TwistAngle 0 TaperAngle 0
step "Sweep4" TwistAngle 0 TaperAngle 0
remove_body "Mirror6" mirrorStitchTolerance 0.1
step "Component Insert39"
fillet "Assemble39" alignAngle 0 alignOffsetX 0 alignOffsetY 0 alignOffsetZ 0
step "WorkPlane" AlongDistance -6
step "Component Insert40"
fillet "Assemble40" alignAngle 0 alignOffsetX 0 alignOffsetY 0 alignOffsetZ 0
step "Component Insert41"
fillet "Assemble41" alignAngle 0 alignOffsetX 0 alignOffsetY 0 alignOffsetZ 0
create_component "CreateComponent5"
remove_body "RemoveBody6"
create_component "CreateComponent6"
remove_body "RemoveBody7"
joint_origin "JointOrigin1"
joint_origin "JointOrigin1"
joint_origin "JointOrigin2"
joint_origin "JointOrigin66"
joint_origin "JointOrigin6"
joint_origin "JointOrigin69"
joint_origin "JointOrigin73"
joint_origin "JointOrigin75"
joint_origin "JointOrigin76"
joint_origin "JointOrigin77"
joint_origin "JointOrigin78"
joint_origin "JointOrigin4"
joint_origin "JointOrigin7"
joint_origin "JointOrigin5"
joint_origin "JointOrigin6"
joint_origin "JointOrigin7"
joint_origin "JointOrigin79"
joint_origin "JointOrigin80"
joint_origin "JointOrigin8"
joint_origin "JointOrigin10"
joint_origin "JointOrigin11"
joint_origin "JointOrigin81"
joint_origin "JointOrigin82"
joint_origin "JointOrigin83"
joint_origin "JointOrigin84"
joint_origin "JointOrigin85"
joint_origin "JointOrigin86"
joint_origin "JointOrigin87"
named bodies: "Hotplate Body", "Rear Cap", "Rotary Cap", "HP Cam Front", "HP Cam Rear", "Circuit Cap"

design "PCB Blade Drop" references "TE-10p-2p5-blade_1123684-07"
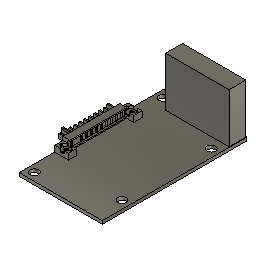
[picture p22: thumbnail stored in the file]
sketch "Sketch1" plane through (0, 0, 0) normal (0, 0, 1) x axis (1, 0, 0)
  line L1 (42, 0) -> (0, 0)
  line L2 (42, 73) -> (42, 0)
  line L3 (0, 73) -> (42, 73)
  line L4 (0, 0) -> (0, 73)
  line L5 (3.7, 20.05) -> (3.7, 52.95)
  line L6 (0, 36.5) -> (3.7, 36.5)
  line L7 (3.7, 20.05) -> (3.7, 4)
  line L8 (3.7, 69) -> (3.7, 52.95)
  line L9 (41.75, 72.75) -> (9.75, 72.75)
  line L10 (41.75, 64.25) -> (41.75, 72.75)
  line L11 (9.75, 64.25) -> (41.75, 64.25)
  line L12 (9.75, 72.75) -> (9.75, 64.25)
  line L13 (31.25, 70.5) -> (20.25, 70.5)
  line L14 (31.25, 66.5) -> (31.25, 70.5)
  line L15 (20.25, 66.5) -> (31.25, 66.5)
  line L16 (20.25, 70.5) -> (20.25, 66.5)
  line L17 (41.75, 64.25) -> (9.75, 72.75)
  line L18 (31.25, 70.5) -> (20.25, 66.5)
  line L19 (38, 59) -> (38, 14)
  circle C1 centre (3.7, 52.95) radius 1.125
  circle C2 centre (3.7, 20.05) radius 1.125
  circle C3 centre (3.7, 69) radius 2.125
  circle C4 centre (3.7, 4) radius 2.125
  circle C5 centre (3.7, 69) radius 3
  circle C6 centre (3.7, 4) radius 3
  circle C7 centre (38, 14) radius 2.125
  circle C8 centre (38, 59) radius 2.125
  point P1 (0, 0)
  point P2 (0, 0)
  point P6 (3.7, 52.95)
  point P8 (3.7, 52.95)
  point P7 (3.7, 20.05)
  point P9 (3.7, 20.05)
  point P10 (3.7, 36.5)
  point P11 (0, 36.5)
  point P13 (3.7, 4)
  point P14 (3.7, 4)
  point P15 (3.7, 20.05)
  point P16 (3.7, 52.95)
  point P12 (3.7, 69)
  point P17 (3.7, 69)
  point P28 (38, 14)
  point P30 (38, 14)
  point P29 (38, 59)
  point P31 (38, 59)
  point P5 (0, 73)
  point P18 (3.7, 69)
  point P19 (3.7, 4)
  point P4 (42, 73)
  point P20 (9.75, 72.75)
  point P21 (41.75, 72.75)
  point P23 (9.75, 64.25)
  point P25 (31.25, 70.5)
  point P26 (31.25, 66.5)
  point P24 (20.25, 70.5)
  horizontal L1
  vertical L2
  horizontal L3
  vertical L4
  coincident P1 P2
  vertical L5
  coincident P6 P8
  coincident P7 P9
  equal C1 C2
  midpoint L5 P10
  midpoint L4 P11
  horizontal L6
  coincident P13 P14
  coincident P9 P15
  coincident P8 P16
  coincident P12 P17
  vertical L8
  vertical L7
  equal L7 L8
  concentric C3 C5
  concentric C4 C6
  equal C3 C4
  equal C5 C6
  horizontal L9
  vertical L10
  horizontal L11
  vertical L12
  horizontal L13
  vertical L14
  horizontal L15
  vertical L16
  midpoint L17 L18
  parallel L2 L19
  coincident P28 P30
  coincident P29 P31
  equal C7 C8
  equal C3 C7
  dimension "d1" distance P6 P7 = 32.9
  dimension "d2" diameter C1 = 2.25
  dimension "d3" distance P10 P11 = 3.7
  dimension "d4" distance P2 P5 = 73
  dimension "d11" diameter C3 = 4.25
  dimension "d12" diameter C5 = 6
  dimension "d13" distance L3 P18 = 4
  dimension "d14" distance P18 P19 = 65
  dimension "d15" distance P4 P5 = 42
  dimension "d16" distance P20 P21 = 32
  dimension "d17" distance P20 P23 = 8.5
  dimension "d18" distance P4 L9 = 0.25
  dimension "d19" distance P4 L10 = 0.25 (= "d18")
  dimension "d20" distance P25 P26 = 4
  dimension "d21" distance P24 P25 = 11
  dimension "d28" distance L2 P28 = 4
  dimension "d29" distance P19 P30 = 10
  dimension "d30" distance P18 P31 = 10
extrude "Extrude1" new body sketch "Sketch1" profile of L1 L2 L3 L4 C1 C2 C3 C4 L9 L10 L11 L12 L13 L14 L15 L16 C7 C8 against normal blind 1.6
extrude "Extrude2" add sketch "Sketch1" profile of L9 L10 L11 L12 L13 L14 L15 L16 along normal blind 25
extrude "Extrude3" add sketch "Sketch1" profile of L13 L14 L15 L16 against normal blind 4
component_insert "Component Insert"
joint "Assemble1" alignAngle 90 alignOffsetX 0 alignOffsetY 0 alignOffsetZ 0
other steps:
joint_origin "JointOrigin1"

design "M3x10-BHCS"
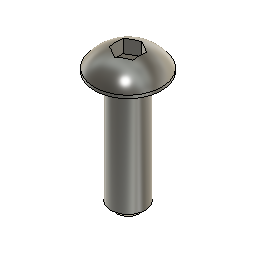
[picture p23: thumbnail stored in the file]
sketch "Sketch1" plane through (0, 0, 0) normal (0, 1, 0) x axis (1, 0, 0)
  line L1 (0, 10) -> (0, -1.65)
  line L2 (0.95, 10) -> (0, 10)
  line L3 (1.45, 9.5) -> (0.95, 10)
  line L4 (1.45, 0) -> (1.45, 9.5)
  line L5 (2.85, 0) -> (1.45, 0)
  line L6 (2.85, -0.25) -> (2.85, 0)
  line L7 (1, -1.65) -> (0, -1.65)
  arc A1 centre (0, 1.5937) radius 3.3944 clockwise from (2.85, -0.25) to (1, -1.65)
  point P1 (0, 0)
  point P10 (0, 1.5937)
  point P3 (0, 10)
  point P2 (0, -1.65)
  point P9 (1, -1.65)
  point P7 (2.85, 0)
  point P8 (2.85, -0.25)
  point P5 (1.45, 9.5)
  vertical L1
  perpendicular L1 L2
  perpendicular L2 L4
  perpendicular L4 L5
  perpendicular L5 L6
  perpendicular L1 L7
  coincident P1 L5
  coincident L1 P10
  coincident P1 L1
  dimension "d1" distance P1 P3 = 10
  dimension "d2" distance P1 P2 = 1.65
  dimension "d3" distance P2 P9 = 1
  dimension "d4" distance P7 P8 = 0.25
  dimension "d5" distance L1 P7 = 2.85 (= "( 5.7 / 2 ) * 1 mm")
  dimension "d6" distance P1 L4 = 1.45 (= "( 2.9 / 2 ) * 1 mm")
  dimension "d7" angle L2 L3 = 45
  dimension "d8" distance L2 P5 = 0.5
revolve "Revolve1" sketch "Sketch1" AlongAngle 360
sketch "Sketch2" plane through (0, 0, 1.65) normal (0, 0, 1) x axis (-1, 0, 0)
  line L1 (0, -1.1547) -> (-1, -0.5774)
  line L2 (1, -0.5774) -> (0, -1.1547)
  line L3 (1, 0.5774) -> (1, -0.5774)
  line L4 (0, 1.1547) -> (1, 0.5774)
  line L5 (-1, 0.5774) -> (0, 1.1547)
  line L6 (-1, -0.5774) -> (-1, 0.5774)
  circle C1 centre (0, 0) radius 1
  point P2 (0, 0)
  point P9 (0, 0)
  point P5 (1, -0.5774)
  coincident P2 P9
  vertical L3
  dimension "d10" distance P5 L6 = 2
extrude "Extrude1" cut sketch "Sketch2" profile of L1 L2 L3 L4 L5 L6 to an object offset 0.5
